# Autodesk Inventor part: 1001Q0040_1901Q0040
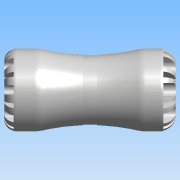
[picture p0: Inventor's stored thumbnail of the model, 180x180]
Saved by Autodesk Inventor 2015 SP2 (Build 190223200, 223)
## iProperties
Created: 2016-12
Part Number: 1001Q0040_1901Q0040
Material: PVC-Piping
Description: PLASSON PVC TO PE COUPLER 40 SERIES 1
Document SubType Name: Modeling
Designer: KIM
Mass: 95.2094 g
Surface Area: 200.83 cm^2
Volume: 68.0067 cm^3
Density: 1.4 g/cm^3
Appearance: Smooth - White
ILogicFactory: False
Author: KIM
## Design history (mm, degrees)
derived "1001Q.ipt"
feature "Solid1::1001Q.ipt"
tag "TaggingFeature1"
body "Solid1"
other parameters: "d11" = 8, "d13" = 8, "d14" = 0, "d16" = 360 deg, "d18" = 8 deg, "d19" = 0.8, "d20" = 8 deg, "d21" = 0.8, "d23" = 0, "d25" = 360 deg, "d27" = 28, "d28" = 12, "d29" = 12, "d30" = 15.68, "d31" = 0, "d33" = 0, "d37" = 29, "d38" = 0.7, "d45" = 29, "d50" = 360 deg, "d54" = 0.513, "d61" = 44, "d63" = 29, "d64" = 145, "d65" = 73, "d66" = 3.33333, "d67" = 72.5, "d70" = 11.7, "d72" = 10.4, "d73" = 0, "d75" = 360 deg, "d77" = 8 deg, "d78" = 8 deg, "d79" = 0.8, "d80" = 0.8, "d82" = 0, "d84" = 360 deg, "d94" = 59.5, "H_" = 145, "l_1" = 73, "d69" = 44, "d71" = 13
